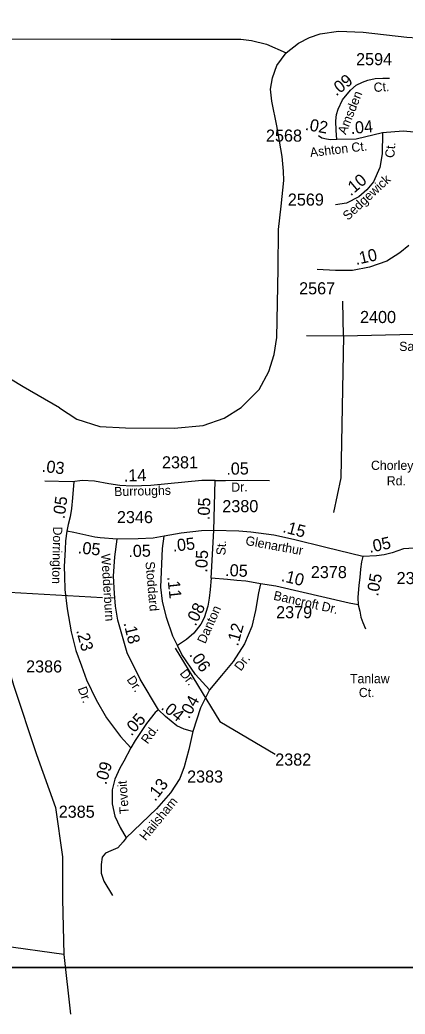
# Model space of a CAD drawing. Extents: x 2290055 to 2389491, y 66597 to 237875.
# Drawn here: x 2330519 to 2332508, y 125554 to 130690 of the extents above; entities that cross this region are included whole.
import ezdxf

# ---------------------------------------------------------------- set-up
doc = ezdxf.new("R2010")
doc.units = 0
for name, color, linetype in [('Exist Road Non-System Type 51', 7, 'Continuous'), ('Exist Road Secondary Mileage Hundredths English Label', 7, 'Continuous'), ('Exist Road Secondary Type 51 Attributed', 7, 'Continuous'), ('Exist Road Secondary Type 51 Label', 7, 'Continuous'), ('Exist Road Secondary Type 51 Number Label', 7, 'Continuous'), ('Map Preparation Inset Cut Line', 7, 'Continuous')]:
    doc.layers.add(name, color=color, linetype=linetype)

msp = doc.modelspace()

# ---------------------------------------------------------------- linework, layer by layer
at = {"layer": 'Exist Road Non-System Type 51'}
for points in [[(2331892.8, 130519.8), (2331957.1, 130570.3), (2332013.9, 130599.3), (2332068.4, 130619), (2332163.2, 130632.7), (2332291, 130626), (2332517.1, 130601.6), (2332677.1, 130591.2), (2332730.8, 130588.3), (2332760.4, 130585.8)], [(2329917.1, 130109.6), (2329993.4, 130145.8), (2330039, 130182.3), (2330079, 130260.6), (2330115.5, 130368.5), (2330152.9, 130453.7), (2330196.4, 130512.9), (2330264.2, 130565.1), (2330340.7, 130589.4), (2330464.2, 130592.9), (2330989.4, 130591.2), (2331659.8, 130591.2), (2331715.4, 130584.2), (2331791.9, 130565.1), (2331892.8, 130519.8)], [(2330723.2, 128686), (2330813.5, 128628.2), (2330931.4, 128590.6), (2331064.4, 128583.1), (2331315.3, 128580.6), (2331465.8, 128595.6), (2331573.7, 128633.3), (2331661.5, 128688.5), (2331754.3, 128781.3), (2331804.5, 128874.2), (2331832.1, 128962.1), (2331844.6, 129049.9), (2331852.1, 129403.8), (2331854.7, 129607.1), (2331867.2, 129727.6), (2331882.3, 129860.6), (2331880, 129909.2), (2331872.2, 129984.7), (2331846.2, 130143.3), (2331820.2, 130270.8), (2331812.4, 130333.2), (2331822.8, 130390.5), (2331846.2, 130455.5), (2331892.8, 130519.8)], [(2332188.8, 129057.1), (2332186.4, 129237.9)], [(2332188.8, 129057.1), (2331998.4, 129058.6)], [(2332188.8, 129057.1), (2332175.4, 128324.1), (2332138.7, 128145.8)], [(2330723.2, 128686), (2330535.1, 128793.9), (2330412.1, 128869.2), (2330301.7, 128929.4), (2330206.2, 128972.7), (2330093.8, 128996.8), (2329973.3, 128984.8), (2329820.7, 128952.6), (2329764.5, 128928.5), (2329559.1, 128800.9), (2329487.4, 128715.6), (2329383, 128583.1), (2329298.7, 128486.6), (2329218.4, 128414.3), (2328960.8, 128196.5), (2328875.5, 128106.2), (2328619.6, 127774.9), (2328494.2, 127639.3), (2328338.6, 127554), (2328173.1, 127523.9), (2328002.5, 127559), (2327877, 127589.1), (2327651.2, 127579.1), (2326564.4, 127550)], [(2330270.4, 128358.1), (2330336.5, 128181.7), (2330350.8, 128022.5), (2330348.7, 127959.2), (2330369.1, 127740.8), (2330418, 127491.6), (2330485.3, 127252.9), (2330604.6, 126894.8), (2330703.5, 126620.8), (2330739.2, 126366.4), (2330738.7, 126148.2), (2330746, 125862.2)], [(2332266, 127668.3), (2332273.4, 127635.4), (2332279.5, 127604.8), (2332289.2, 127578), (2332303.9, 127543.8)], [(2330746, 125862.2), (2330423.7, 125906.2), (2330144.1, 125987.6), (2329781.9, 126169.9), (2329538.9, 126337), (2329331.1, 126510.9), (2329129.8, 126683.9), (2329096.1, 126742.7), (2329071.1, 126827.6), (2329105.9, 126948.4), (2329133.1, 127174.8), (2329152.7, 127247.7), (2329189.7, 127321.7), (2329224.2, 127387.3)], [(2331068, 126465), (2331051.5, 126444.2), (2331024.6, 126413.7), (2330988, 126397.8), (2330961.1, 126385.6), (2330944, 126364.8), (2330937.9, 126326.9), (2330939.1, 126281.7), (2330952.6, 126241.4), (2330997.7, 126166.9)], [(2330746, 125862.2), (2330779.7, 125554.3)]]:
    msp.add_lwpolyline(points, dxfattribs=at)
at = {"layer": 'Exist Road Secondary Type 51 Attributed'}
for points in [[(2332155.6, 130072.4), (2332151, 130119.4), (2332150.6, 130169.3), (2332153.7, 130201.5), (2332162, 130229.2), (2332184.6, 130276.7), (2332225, 130327.8), (2332255, 130352.6), (2332286.8, 130367.8), (2332315.7, 130379.2), (2332352.9, 130387.5), (2332392.3, 130389.1), (2332426.7, 130388.9)], [(2332391.2, 130106.9), (2332388.6, 129997.5), (2332376.6, 129927), (2332344.6, 129854.5), (2332310.6, 129811.9), (2332267.9, 129776.7), (2332205.1, 129743.7), (2332147.5, 129734.1)], [(2332391.2, 130106.9), (2332254.8, 130074.8), (2332155.6, 130072.4)], [(2332730.8, 130081.2), (2332611.1, 130105.7), (2332497.9, 130114.7), (2332391.2, 130106.9)], [(2332155.6, 130072.4), (2332122.2, 130069.9), (2332101.7, 130073.5), (2332078.5, 130079.5), (2332060.5, 130091.5)], [(2332526.3, 129524.5), (2332480.2, 129487.1), (2332413.7, 129443.9), (2332323.2, 129412.5), (2332235.4, 129396), (2332148.7, 129396), (2332053.2, 129401.5)], [(2333301.9, 129082.4), (2333152.6, 129073.6), (2332916.9, 129068.2), (2332697.3, 129068.2), (2332188.8, 129057.1)], [(2330791.4, 128304.6), (2330648.5, 128306.7)], [(2330796.9, 128305.9), (2330791.4, 128222), (2330785.9, 128165.6), (2330779.1, 128123), (2330768.1, 128083.1), (2330760.9, 128049.3)], [(2331527, 128310.1), (2331458.2, 128310.1), (2331195.6, 128285.3), (2331099.4, 128281.2), (2331034.8, 128285.3), (2330978.4, 128293.6), (2330904.2, 128307.3), (2330840.9, 128310.1), (2330791.4, 128304.6)], [(2331520.3, 128053), (2331527, 128310.1)], [(2331527, 128310.1), (2331580.6, 128311.4), (2331693.3, 128312.8), (2331807.4, 128311.4)], [(2330760.9, 128049.3), (2330754.8, 127999.2), (2330752.3, 127954), (2330748.1, 127867.3), (2330749.3, 127816), (2330751.7, 127747.6), (2330762.7, 127647.4), (2330783.5, 127528.9), (2330808.5, 127432.4), (2330837.8, 127353), (2330862.2, 127281), (2330913.5, 127177.1), (2330966, 127085.5), (2331038.7, 126987.8), (2331091.2, 126929.2)], [(2331020.9, 128007.8), (2330933.8, 128015.1), (2330905.6, 128017.3), (2330858.6, 128028.5), (2330797.5, 128042), (2330760.9, 128049.3)], [(2331520.3, 128053), (2331455.9, 128050.6), (2331351.8, 128039.3), (2331263, 128022.6)], [(2331506.3, 127806.2), (2331520.3, 128053)], [(2332288.9, 127917.4), (2332099.1, 127965), (2331930.6, 128005.3), (2331829.2, 128028.5), (2331710.5, 128044.6), (2331650, 128048.7), (2331520.3, 128053)], [(2331235.2, 127125.8), (2331140.6, 127284.6), (2331072.2, 127421.4), (2331025.2, 127588.8), (2331013, 127662.1), (2331006.9, 127726.8), (2331002, 127816), (2331008.7, 127916.2), (2331020.9, 128007.8)], [(2331263, 128022.6), (2331206.6, 128013), (2331129.6, 128009), (2331020.9, 128007.8)], [(2331332.3, 127458.1), (2331307.9, 127506.9), (2331275.5, 127603.4), (2331256, 127687.7), (2331246.2, 127759.8), (2331256, 127958.9), (2331263, 128022.6)], [(2332554, 127961.4), (2332498.9, 127957.5), (2332440.4, 127937.1), (2332399.8, 127927.6), (2332360.4, 127921.6), (2332288.9, 127917.4)], [(2332288.9, 127917.4), (2332282.8, 127890.5), (2332277.3, 127853.3), (2332273.1, 127809.9), (2332269.4, 127769.8), (2332263.8, 127705.6), (2332266, 127668.3)], [(2331506.3, 127806.2), (2331501.4, 127747.6), (2331496.5, 127702.4), (2331489.2, 127662.1), (2331469.7, 127601), (2331452.6, 127569.2), (2331417.2, 127521.6), (2331379.8, 127489.7), (2331332.3, 127458.1)], [(2331760.7, 127776.3), (2331734, 127782.4), (2331684.8, 127790.6), (2331639, 127794), (2331590.5, 127798.9), (2331506.3, 127806.2)], [(2331760.7, 127776.3), (2331750.5, 127730.5), (2331734.6, 127640.1), (2331715.7, 127557), (2331677.8, 127467.9), (2331620.4, 127375), (2331559.4, 127304.2), (2331497.1, 127230.3)], [(2332266, 127668.3), (2332218.1, 127678), (2331840, 127765.3), (2331760.7, 127776.3)], [(2331497.1, 127230.3), (2331426.3, 127309.1), (2331354.3, 127411.7), (2331332.3, 127458.1)], [(2331497.1, 127230.3), (2331450.6, 127135.9), (2331412.3, 127013.4)], [(2331235.2, 127125.8), (2331216.9, 127112.4), (2331173, 127056.2), (2331114.4, 126967), (2331091.2, 126929.2)], [(2331409.8, 127014.7), (2331367.1, 127026.9), (2331329.2, 127044), (2331270.6, 127091.6), (2331235.2, 127125.8)], [(2331412.3, 127013.4), (2331391.5, 126921.8), (2331367.1, 126831.4), (2331343.9, 126771.6), (2331296, 126696.7), (2331224.5, 126615.5), (2331068, 126465)], [(2331091.2, 126929.2), (2331055.7, 126860.7), (2331035, 126825.2), (2331009.3, 126767.9), (2330995.9, 126712.9), (2330995.9, 126640.9), (2331009.3, 126577.4), (2331036.2, 126517.5), (2331068, 126465)]]:
    msp.add_lwpolyline(points, dxfattribs=at)
at = {"layer": 'Exist Road Secondary Type 51 Number Label'}
msp.add_line((2330945.2, 127704.8), (2330335.6, 127740.3), dxfattribs=at)
msp.add_lwpolyline([(2331321.1, 127444.3), (2331551.9, 127065.5), (2331836.1, 126896.8)], dxfattribs=at)
at = {"layer": 'Map Preparation Inset Cut Line'}
for points in [[(2326073, 125795.4), (2326049.1, 134004.6), (2335243.2, 134004.6), (2335243.2, 141886.2), (2343900.4, 141886.2), (2341393.8, 134004.6), (2339225, 125795.4)], [(2341393.8, 134004.6), (2335243.2, 134004.6), (2326049.1, 134004.6), (2326073, 125795.4), (2339225, 125795.4)]]:
    msp.add_lwpolyline(points, close=True, dxfattribs=at)

# ---------------------------------------------------------------- texts
at = {"layer": 'Exist Road Secondary Mileage Hundredths English Label'}
for s, rotation, p in [('.09', 38.4377, (2332152.1, 130294)), ('.02', 349.8684, (2331988.5, 130122.7)), ('.04', 5.1547, (2332228.5, 130100.2)), ('.10', 40.1518, (2332226.5, 129778)), ('.10', 12.766, (2332254.7, 129423.8)), ('.03', 353.2102, (2330630, 128356.1)), ('.05', 0.9396, (2331585, 128340.3)), ('.14', 1.4916, (2331056.1, 128304.9)), ('.05', 82.0965, (2330749.1, 128110)), ('.05', 87.5556, (2331497.9, 128105.4)), ('.15', 345.1895, (2331872.1, 128044.6)), ('.05', 354.0777, (2330816.1, 127934.7)), ('.05', 6.2103, (2331310.3, 127942.8)), ('.05', 12.3329, (2332325.1, 127936.4)), ('.05', 1.309, (2331079.4, 127914.9)), ('.05', 87.3624, (2331485.8, 127834.5)), ('.05', 357.4254, (2331577.7, 127817.8)), ('.10', 346.322, (2331864.5, 127792.1)), ('.11', 276.2964, (2331279.5, 127813)), ('.05', 79.396, (2332367.8, 127710.2)), ('.08', 63.805, (2331426, 127555.3)), ('.23', 285.4367, (2330809.1, 127535.8)), ('.18', 283.6758, (2331053.6, 127574.4)), ('.12', 74.6066, (2331644.5, 127451.8)), ('.06', 304.1686, (2331391.2, 127411.1)), ('.04', 61.1803, (2331391.8, 127076)), ('.04', 322.0716, (2331243.5, 127132.6)), ('.05', 47.8759, (2331094.7, 126987.7)), ('.09', 73.8629, (2330964.3, 126735.8)), ('.13', 52.4402, (2331217.4, 126649.6))]:
    msp.add_text(s, height=62.5, rotation=rotation, dxfattribs=at).set_placement(p)
at = {"layer": 'Exist Road Secondary Type 51 Label'}
for s, rotation, p in [('Ct.', 3.6273, (2332346.7, 130317.5)), ('Amsden', 68.2203, (2332201.4, 130094.7)), ('Ashton Ct.', 6.6929, (2332019.2, 129981.7)), ('Ct.', 85.6113, (2332451.5, 129975.8)), ('Sedgewick ', 42.8918, (2332212.2, 129651.6)), ('Sago Bay', 0.3219, (2332477.3, 128979.8)), ('Dr.', 1.403, (2331610.7, 128252.5)), ('Burroughs', 1.403, (2331006.3, 128229.8)), ('Dorrington', 268.862, (2330691, 128073.3)), ('St.', 86.5807, (2331579.5, 127923.3)), ('Glenarthur', 349.6953, (2331680.8, 127978.5)), ('Wedderburn', 273.6429, (2330938.5, 127931.3)), ('Stoddard', 275.0565, (2331166.9, 127890.6)), ('Bancroft Dr.', 347.2981, (2331825.1, 127695.5)), ('Danton', 66.0771, (2331475.7, 127464.2)), ('Dr.', 52.8208, (2331659.5, 127323)), ('Dr.', 307.7915, (2331341.7, 127313.8)), ('Dr.', 304.4212, (2331068.3, 127282.4)), ('Tanlaw  ', 360, (2332223, 127263.8)), ('Dr.', 290.4726, (2330816.9, 127236.1)), ('Rd.', 53.6156, (2331178.6, 126946.1)), ('Tevoit', 93.7524, (2331081.4, 126589)), ('Hailsham', 50.7285, (2331168.6, 126446.5))]:
    msp.add_text(s, height=47.5, rotation=rotation, dxfattribs=at).set_placement(p)
for s, p in [('Chorley', (2332331.4, 128365.5)), ('Rd.', (2332412.8, 128285.7)), ('Ct.', (2332268.7, 127191.9))]:
    msp.add_text(s, height=47.5, dxfattribs=at).set_placement(p)
at = {"layer": 'Exist Road Secondary Type 51 Number Label'}
for s, p in [('2594', (2332254.4, 130456.2)), ('2568', (2331789.3, 130061.3)), ('2569', (2331902.2, 129730.8)), ('2567', (2331960.4, 129272.5)), ('2400', (2332274.8, 129124.2)), ('2381', (2331252.5, 128373.5)), ('2380', (2331563.9, 128147.2)), ('2346', (2331019.9, 128090.6)), ('2378', (2332020.9, 127806.6)), ('2347', (2332463.7, 127775.7)), ('2379', (2331841.8, 127599.3)), ('2386', (2330550.9, 127319.2)), ('2382', (2331837.1, 126838.2)), ('2383', (2331382, 126750.4)), ('2385', (2330719.3, 126568.7))]:
    msp.add_text(s, height=62.5, dxfattribs=at).set_placement(p)

doc.saveas('drawing.dxf')
